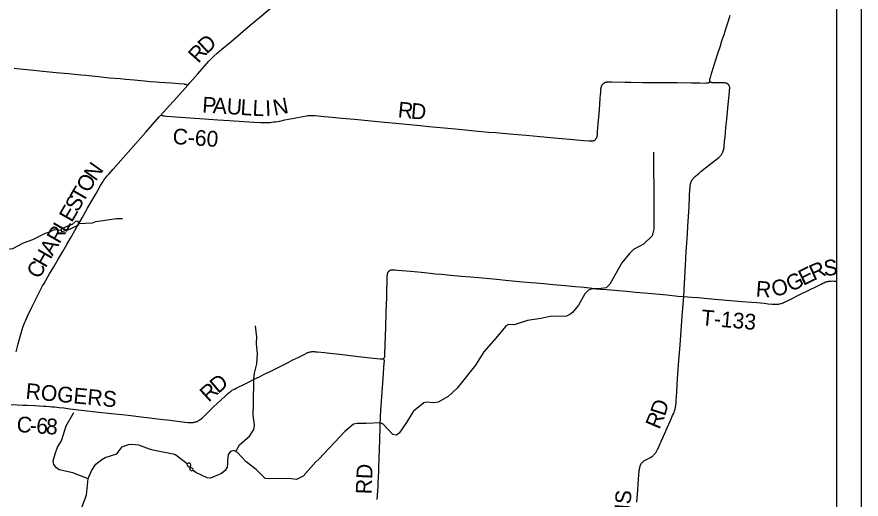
# Model space of a CAD drawing. Extents: x -5.4 to 49.9, y 13.2 to 48.4.
# Drawn here: x 30.118 to 33.165, y 44.845 to 46.585 of the extents above; entities that cross this region are included whole.
import ezdxf

# ---------------------------------------------------------------- set-up
doc = ezdxf.new("R2010")
doc.units = 0
for name, color, linetype in [('GM_X_County_Road', 7, 'Continuous'), ('GM_X_County_Road_Text', 7, 'Continuous'), ('GM_X_Major_River', 7, 'Continuous'), ('GM_X_Minor_Lake', 7, 'Continuous'), ('GM_X_Minor_River', 7, 'Continuous'), ('GM_X_Township', 7, 'Continuous'), ('GM_X_Township_Road', 7, 'Continuous'), ('GM_X_Township_Road_Text', 7, 'Continuous'), ('SH_Data', 7, 'Continuous')]:
    doc.layers.add(name, color=color, linetype=linetype)

msp = doc.modelspace()

# ---------------------------------------------------------------- linework, layer by layer
at = {"layer": 'GM_X_County_Road'}
for points in [[(30.7351, 46.3393), (30.7424, 46.3474), (30.7528, 46.3589), (30.7707, 46.3795), (30.8111, 46.4252), (30.8205, 46.4352), (30.8248, 46.4396), (30.8289, 46.4435), (30.8413, 46.4549), (30.8497, 46.4622), (30.8573, 46.4687), (30.8896, 46.4959), (30.9249, 46.5254), (30.9601, 46.5549), (30.9941, 46.5831), (31.0471, 46.6271)], [(30.6373, 46.2311), (30.6401, 46.2302), (30.6418, 46.2296), (30.6436, 46.2292), (30.646, 46.2286), (30.6485, 46.2281), (30.6515, 46.2277), (30.6577, 46.2271), (30.6918, 46.2248), (30.7427, 46.2213), (30.7786, 46.2187), (30.8431, 46.2143), (30.8846, 46.2117), (30.9727, 46.2059), (30.9981, 46.2044), (31.0093, 46.204), (31.0134, 46.204), (31.0174, 46.204), (31.0224, 46.2041), (31.0273, 46.2044), (31.0323, 46.2047), (31.0385, 46.2053), (31.0448, 46.206), (31.0514, 46.207), (31.059, 46.2082), (31.0667, 46.2095), (31.0856, 46.2133), (31.1246, 46.2211), (31.1502, 46.2262), (31.1629, 46.2285), (31.168, 46.2293), (31.1712, 46.2296), (31.1745, 46.2299), (31.1781, 46.23), (31.1814, 46.23), (31.1847, 46.2299), (31.1898, 46.2295), (31.1947, 46.2291), (31.2268, 46.2263), (31.2559, 46.2235), (31.2905, 46.2202), (31.3363, 46.2158), (31.3852, 46.2114), (31.4328, 46.2068), (31.486, 46.2018), (31.5738, 46.193), (31.6054, 46.19), (31.632, 46.1875), (31.6605, 46.1848), (31.6994, 46.1811), (31.7124, 46.1799), (31.7365, 46.1777), (31.7706, 46.1743), (31.8201, 46.1698), (31.8473, 46.1675), (31.8962, 46.1633), (31.9563, 46.158), (32.007, 46.1532), (32.0702, 46.148), (32.1271, 46.1431), (32.163, 46.1398), (32.1835, 46.1379), (32.1891, 46.1375), (32.1909, 46.1374), (32.1928, 46.1375), (32.1945, 46.1376), (32.1958, 46.1378), (32.1971, 46.138), (32.1984, 46.1383), (32.1997, 46.1387), (32.2012, 46.1393), (32.2023, 46.1398), (32.204, 46.1408), (32.2054, 46.1419), (32.2068, 46.1431), (32.2076, 46.144), (32.2082, 46.1448), (32.2091, 46.146), (32.21, 46.1476), (32.2109, 46.1495), (32.2115, 46.1511), (32.212, 46.1528), (32.2125, 46.1546), (32.2129, 46.1567), (32.2132, 46.1589), (32.214, 46.1676), (32.2154, 46.1856), (32.2175, 46.2123), (32.2193, 46.2352), (32.2219, 46.2674), (32.2239, 46.2934), (32.2246, 46.3027), (32.2253, 46.3133), (32.2256, 46.317), (32.2259, 46.3219), (32.2263, 46.3251), (32.2265, 46.3264), (32.2267, 46.3277), (32.227, 46.3294), (32.2274, 46.3313), (32.2278, 46.333), (32.2282, 46.3342), (32.2285, 46.3354), (32.2291, 46.3368), (32.2296, 46.3379), (32.2302, 46.3391), (32.231, 46.3404), (32.2318, 46.3415), (32.2327, 46.3427), (32.2337, 46.3437), (32.235, 46.345), (32.2362, 46.3459), (32.2375, 46.3468), (32.2386, 46.3474), (32.2402, 46.3483), (32.2418, 46.3489), (32.2429, 46.3493), (32.2445, 46.3497), (32.2459, 46.35), (32.2476, 46.3503), (32.2492, 46.3505), (32.2513, 46.3507), (32.2537, 46.3508), (32.2648, 46.3507), (32.312, 46.3496), (32.3338, 46.3494), (32.3773, 46.3491), (32.4077, 46.3489), (32.4512, 46.3485), (32.5016, 46.348), (32.5513, 46.3474), (32.5836, 46.3469), (32.601, 46.3467), (32.6072, 46.3468), (32.6091, 46.3469), (32.6109, 46.3471), (32.6122, 46.3473), (32.6134, 46.3475), (32.6145, 46.3479), (32.6158, 46.3484), (32.617, 46.3488), (32.6182, 46.3494), (32.6197, 46.35), (32.621, 46.3508)], [(30.6373, 46.2311), (30.6565, 46.2525), (30.6948, 46.2949), (30.7351, 46.3393)], [(30.1151, 45.3767), (30.1226, 45.4055), (30.1322, 45.4402), (30.1342, 45.4472), (30.1363, 45.454), (30.1379, 45.4593), (30.1399, 45.4652), (30.142, 45.4711), (30.1445, 45.4775), (30.147, 45.4837), (30.15, 45.4907), (30.1529, 45.4973), (30.1567, 45.5054), (30.1724, 45.5379), (30.189, 45.5719), (30.2004, 45.5948), (30.2108, 45.6146), (30.216, 45.6236), (30.2231, 45.6362), (30.2358, 45.6576), (30.251, 45.6832), (30.2661, 45.7089), (30.2836, 45.739), (30.2979, 45.7638), (30.3114, 45.7868), (30.332, 45.823), (30.3533, 45.8602), (30.3732, 45.8953), (30.3862, 45.9179), (30.4035, 45.9482), (30.4198, 45.9768), (30.4256, 45.9864), (30.4288, 45.9912), (30.432, 45.9956), (30.4355, 46.0004), (30.4395, 46.0056), (30.444, 46.0112), (30.4494, 46.0176), (30.4653, 46.0359), (30.5191, 46.097), (30.5831, 46.1698), (30.6316, 46.2247), (30.6373, 46.2311)], [(31.4417, 45.3527), (31.4422, 45.3531), (31.4429, 45.3537), (31.4436, 45.3544), (31.4442, 45.3552), (31.4446, 45.3558), (31.445, 45.3565), (31.4453, 45.3573), (31.4456, 45.3581), (31.4458, 45.359), (31.4461, 45.3622), (31.4465, 45.3709), (31.4475, 45.4001), (31.4486, 45.4324), (31.4497, 45.4659), (31.4513, 45.52), (31.4527, 45.574), (31.4537, 45.6044), (31.4543, 45.6243), (31.4546, 45.6374), (31.4548, 45.6479), (31.455, 45.6511), (31.4552, 45.6537), (31.4555, 45.6558), (31.4559, 45.6577), (31.4562, 45.6593), (31.4566, 45.6605), (31.457, 45.6616), (31.4574, 45.6626), (31.4579, 45.6637), (31.4585, 45.6648), (31.4592, 45.6657), (31.46, 45.6666), (31.4609, 45.6677), (31.4619, 45.6685), (31.4628, 45.6692), (31.4638, 45.6699), (31.4648, 45.6706), (31.4658, 45.6711), (31.467, 45.6716), (31.4681, 45.672), (31.4695, 45.6724), (31.4711, 45.6726), (31.4723, 45.6727), (31.4738, 45.6728), (31.4754, 45.6729), (31.4775, 45.6729), (31.4795, 45.6728), (31.4836, 45.6724), (31.4935, 45.6715), (31.5079, 45.67), (31.5387, 45.6673), (31.5647, 45.6648), (31.5889, 45.6623), (31.6093, 45.6604), (31.6291, 45.6585), (31.6501, 45.6564), (31.6835, 45.6533), (31.7229, 45.6498), (31.7558, 45.6469), (31.7851, 45.6442), (31.8377, 45.6394), (31.8607, 45.6371), (31.8815, 45.6351), (31.9068, 45.6329), (31.9445, 45.6294), (31.9724, 45.6268), (31.9928, 45.625), (32.0194, 45.6226), (32.0543, 45.6195), (32.0966, 45.6157), (32.1332, 45.6124), (32.1656, 45.6093), (32.1942, 45.6059), (32.2015, 45.605), (32.2084, 45.6044), (32.2243, 45.603), (32.2476, 45.6011), (32.3182, 45.5953), (32.351, 45.5923), (32.3826, 45.5894), (32.424, 45.5855), (32.4634, 45.5817), (32.5035, 45.5777), (32.5249, 45.576)], [(30.0967, 45.1867), (30.1188, 45.1854), (30.1402, 45.1843), (30.1544, 45.1836), (30.1832, 45.1823), (30.2136, 45.1808), (30.2235, 45.1803), (30.2353, 45.1794), (30.2445, 45.1785), (30.2537, 45.1776), (30.2704, 45.1758), (30.2868, 45.1739), (30.3092, 45.1712), (30.3402, 45.1672), (30.3718, 45.1634), (30.3926, 45.1611), (30.4251, 45.1578), (30.4474, 45.1556), (30.4716, 45.1531), (30.497, 45.1505), (30.5196, 45.1479), (30.5387, 45.1455), (30.5567, 45.1432), (30.5759, 45.1407), (30.5979, 45.138), (30.6246, 45.1348), (30.6472, 45.1321), (30.6711, 45.1292), (30.6982, 45.126), (30.7244, 45.123), (30.735, 45.1217), (30.7411, 45.1211), (30.7458, 45.1208), (30.7488, 45.1209), (30.7513, 45.1212), (30.7539, 45.1216), (30.7564, 45.1221), (30.7604, 45.123), (30.7627, 45.1235), (30.7649, 45.1242), (30.7666, 45.1248), (30.7681, 45.1254), (30.7702, 45.1263), (30.772, 45.1273), (30.7738, 45.1282), (30.7758, 45.1293), (30.7777, 45.1306), (30.7799, 45.1321), (30.7834, 45.1347), (30.7882, 45.1386), (30.7914, 45.1416), (30.805, 45.155), (30.8161, 45.1661), (30.828, 45.1776), (30.8411, 45.1899), (30.8545, 45.2023), (30.8697, 45.2164), (30.8786, 45.2245), (30.8838, 45.2291), (30.8874, 45.232), (30.89, 45.234), (30.8912, 45.235), (30.8927, 45.2361), (30.8954, 45.2378), (30.898, 45.2393), (30.9036, 45.2422), (30.9099, 45.2454), (30.9166, 45.2486), (30.9348, 45.2575), (30.9543, 45.2672), (30.9743, 45.2772), (30.9932, 45.2867), (31.011, 45.2955), (31.0272, 45.3033), (31.0485, 45.314), (31.0824, 45.331), (31.0968, 45.3382), (31.1144, 45.347), (31.1355, 45.3576), (31.1472, 45.3635), (31.1622, 45.371), (31.165, 45.3723), (31.1679, 45.3735), (31.1706, 45.3745), (31.1734, 45.3754), (31.1759, 45.3761), (31.1771, 45.3763), (31.1781, 45.3765), (31.1804, 45.3768), (31.183, 45.3771), (31.1852, 45.3773), (31.1873, 45.3773), (31.1891, 45.3773), (31.1924, 45.3771), (31.1953, 45.377), (31.1976, 45.3768), (31.2028, 45.3764), (31.2288, 45.3736), (31.2481, 45.3715), (31.2832, 45.3675), (31.33, 45.362), (31.3615, 45.3585), (31.3937, 45.3549), (31.4177, 45.3521), (31.4294, 45.3511), (31.4321, 45.3508), (31.4343, 45.3507), (31.4363, 45.3507), (31.4373, 45.3508), (31.4383, 45.351), (31.4392, 45.3513), (31.44, 45.3516), (31.4408, 45.3521), (31.4417, 45.3527)]]:
    msp.add_lwpolyline(points, dxfattribs=at)
at = {"layer": 'GM_X_Major_River'}
for points in [[(32.4155, 46.097), (32.417, 45.9063), (32.4167, 45.8186), (32.4106, 45.7951), (32.3801, 45.765), (32.3441, 45.746), (32.3295, 45.7318), (32.3016, 45.6982), (32.2588, 45.6205), (32.2449, 45.6078), (32.2191, 45.6038), (32.1949, 45.6039), (32.1812, 45.5989), (32.168, 45.5855), (32.1453, 45.5453), (32.124, 45.5188), (32.1143, 45.5106), (32.1014, 45.5056), (32.0431, 45.5041), (32.0199, 45.4992), (32.0096, 45.4964), (31.9614, 45.4898), (31.9127, 45.4741), (31.8923, 45.4749), (31.8812, 45.4683), (31.8463, 45.4253), (31.8033, 45.3764), (31.7732, 45.3284), (31.7072, 45.2451), (31.6745, 45.215), (31.6389, 45.1944), (31.6218, 45.1925), (31.5969, 45.1949), (31.5866, 45.1921), (31.5497, 45.1617), (31.5317, 45.1332), (31.5239, 45.1216), (31.4974, 45.0826), (31.4878, 45.0752), (31.4754, 45.0785), (31.4402, 45.1149), (31.4304, 45.1204), (31.3786, 45.118), (31.3457, 45.1183), (31.3324, 45.1156), (31.3016, 45.0885), (31.2076, 44.9893), (31.1965, 44.9789), (31.1508, 44.9282), (31.1267, 44.9158), (31.0999, 44.9194), (31.0258, 44.9186), (31.014, 44.9196), (30.9814, 44.9518), (30.9452, 44.9791), (30.9145, 45.0127), (30.9007, 45.0199), (30.8893, 45.0171), (30.8807, 45.0062), (30.8784, 44.9846), (30.8781, 44.9717), (30.8768, 44.9607), (30.8697, 44.9483), (30.8563, 44.9372), (30.8162, 44.9202), (30.8045, 44.9212), (30.7636, 44.9406), (30.7522, 44.9489)], [(30.2375, 44.6265), (30.2685, 44.6593), (30.3288, 44.7428), (30.341, 44.7703), (30.3457, 44.793), (30.3528, 44.8073), (30.3537, 44.8179), (30.3689, 44.859), (30.3758, 44.9196), (30.3869, 44.9463), (30.4033, 44.9707), (30.4248, 44.9881), (30.4363, 44.9955), (30.479, 45.0086), (30.498, 45.0333), (30.5209, 45.0416), (30.533, 45.0433), (30.5572, 45.0409), (30.5955, 45.0264), (30.6083, 45.0227), (30.6821, 45.0083), (30.6919, 45.0043), (30.7325, 44.9739)], [(30.7325, 44.9739), (30.7318, 44.971), (30.7324, 44.9671), (30.7346, 44.964), (30.7372, 44.9616), (30.7406, 44.9616), (30.7444, 44.963), (30.746, 44.9656), (30.7457, 44.9691), (30.7442, 44.9729), (30.7413, 44.9742), (30.739, 44.9749), (30.7363, 44.975), (30.7356, 44.9746)], [(30.7325, 44.9739), (30.7356, 44.9746)], [(30.7412, 44.9536), (30.7423, 44.952), (30.7445, 44.9493), (30.7471, 44.9478), (30.7494, 44.9473), (30.7513, 44.9481), (30.7525, 44.9492), (30.7537, 44.9526), (30.753, 44.9553), (30.75, 44.9568), (30.747, 44.958), (30.7454, 44.9577)], [(30.7454, 44.9577), (30.7412, 44.9536)]]:
    msp.add_lwpolyline(points, dxfattribs=at)
at = {"layer": 'GM_X_Minor_Lake'}
for points in [[(30.2786, 45.8106), (30.2991, 45.8159), (30.3136, 45.8214), (30.3351, 45.8324), (30.3412, 45.8364), (30.3395, 45.8486), (30.3289, 45.8473), (30.3173, 45.8365), (30.3036, 45.8318), (30.2872, 45.8238), (30.2787, 45.8197)], [(30.2787, 45.8197), (30.2775, 45.8185), (30.2768, 45.8163), (30.2772, 45.8126), (30.2786, 45.8106)], [(30.2375, 44.6265), (30.2685, 44.6593), (30.3288, 44.7428), (30.341, 44.7703), (30.3457, 44.793), (30.3528, 44.8073), (30.3537, 44.8179), (30.3689, 44.859), (30.3758, 44.9196), (30.3869, 44.9463), (30.4033, 44.9707), (30.4248, 44.9881), (30.4363, 44.9955), (30.479, 45.0086), (30.498, 45.0333), (30.5209, 45.0416), (30.533, 45.0433), (30.5572, 45.0409), (30.5955, 45.0264), (30.6083, 45.0227), (30.6821, 45.0083), (30.6919, 45.0043), (30.7325, 44.9739)]]:
    msp.add_lwpolyline(points, dxfattribs=at)
at = {"layer": 'GM_X_Minor_River'}
for points in [[(30.3408, 45.8393), (30.3913, 45.842), (30.4031, 45.8463), (30.478, 45.8579), (30.4996, 45.8579)], [(29.3473, 45.56), (29.3917, 45.5706), (29.4934, 45.6212), (29.5186, 45.6299), (29.6255, 45.6534), (29.6936, 45.6909), (29.7377, 45.7167), (29.7686, 45.7302), (29.8055, 45.7368), (29.862, 45.738), (30.0475, 45.7533), (30.0804, 45.747), (30.1035, 45.7492), (30.1418, 45.7698), (30.1754, 45.7813), (30.2213, 45.8044), (30.2331, 45.8084), (30.2541, 45.8183), (30.2769, 45.8155)], [(30.908, 45.0161), (30.922, 45.0406), (30.9578, 45.0723), (30.9734, 45.0963), (30.9752, 45.1115), (30.9713, 45.1477), (30.972, 45.1895), (30.9728, 45.2776), (30.9751, 45.2989), (30.984, 45.3336), (30.987, 45.3693), (30.9831, 45.4066), (30.9846, 45.429), (30.9793, 45.4706)], [(30.3757, 44.9185), (30.3199, 44.9391), (30.2705, 44.9507), (30.2607, 44.9573), (30.2518, 44.9696), (30.2487, 44.9826), (30.2556, 45.0083), (30.264, 45.0329), (30.2784, 45.0546), (30.296, 45.1098), (30.3238, 45.1572)]]:
    msp.add_lwpolyline(points, dxfattribs=at)
at = {"layer": 'GM_X_Township'}
msp.add_lwpolyline([(33.0771, 44.431), (33.0771, 47.4437), (28.0105, 47.4437)], dxfattribs=at)
at = {"layer": 'GM_X_Township_Road'}
for points in [[(32.621, 46.3508), (32.6205, 46.3515), (32.6201, 46.3524), (32.6198, 46.3532), (32.6196, 46.3541), (32.6194, 46.355), (32.6194, 46.3563), (32.6194, 46.3575), (32.6194, 46.3584), (32.6196, 46.3596), (32.6198, 46.3606), (32.6211, 46.366), (32.624, 46.3761), (32.6316, 46.4004), (32.6376, 46.4194), (32.6485, 46.4531), (32.6573, 46.4804), (32.6631, 46.4988), (32.6704, 46.5213), (32.6784, 46.5462), (32.6867, 46.5717), (32.6931, 46.5917)], [(30.1084, 46.4003), (30.1288, 46.3983), (30.1671, 46.3943), (30.211, 46.39), (30.2593, 46.3852), (30.3044, 46.3808), (30.3489, 46.3763), (30.3662, 46.3745), (30.378, 46.3733), (30.3891, 46.3722), (30.4218, 46.3688), (30.4521, 46.3658), (30.4905, 46.3624), (30.5112, 46.3604), (30.5412, 46.3577), (30.5787, 46.3544), (30.6004, 46.3527), (30.6219, 46.3509), (30.633, 46.3501), (30.6544, 46.3486), (30.6761, 46.3472), (30.7023, 46.345), (30.7212, 46.3432), (30.7235, 46.343), (30.7254, 46.3427), (30.7275, 46.3423), (30.729, 46.3418), (30.732, 46.3406), (30.7351, 46.3393)], [(32.5249, 45.576), (32.5264, 45.5995), (32.5278, 45.6272), (32.5284, 45.6396), (32.5302, 45.67), (32.5313, 45.6874), (32.5329, 45.7134), (32.5342, 45.7376), (32.5362, 45.7686), (32.5383, 45.8021), (32.5399, 45.8306), (32.5441, 45.9001), (32.5461, 45.9367), (32.5474, 45.9646), (32.5477, 45.9689), (32.5481, 45.9729), (32.5485, 45.9757), (32.5488, 45.9782), (32.549, 45.9798), (32.5493, 45.981), (32.5496, 45.9824), (32.5499, 45.9839), (32.5504, 45.9855), (32.5511, 45.9875), (32.5516, 45.989), (32.5521, 45.9904), (32.5529, 45.9921), (32.5535, 45.9933), (32.5541, 45.9945), (32.5548, 45.9956), (32.5556, 45.9969), (32.5565, 45.9983), (32.5579, 46.0002), (32.5591, 46.0018), (32.5627, 46.0061), (32.5676, 46.0109), (32.5732, 46.0158), (32.5804, 46.0217), (32.5872, 46.0272), (32.615, 46.0491), (32.6408, 46.0696), (32.6516, 46.0784), (32.6549, 46.0815), (32.6566, 46.0831), (32.6579, 46.0844), (32.6589, 46.0856), (32.66, 46.087), (32.6612, 46.0885), (32.6622, 46.09), (32.6629, 46.0912), (32.664, 46.0929), (32.6649, 46.0946), (32.6657, 46.0962), (32.6662, 46.0974), (32.6666, 46.0985), (32.6672, 46.1), (32.6678, 46.1014), (32.6684, 46.1034), (32.6688, 46.105), (32.6692, 46.1068), (32.6695, 46.1086), (32.6698, 46.1105), (32.6704, 46.1143), (32.671, 46.1191), (32.6726, 46.1358), (32.674, 46.1507), (32.6771, 46.1853), (32.6802, 46.2168), (32.6852, 46.2694), (32.6888, 46.3028), (32.6901, 46.3164), (32.6907, 46.3227), (32.6911, 46.3271), (32.6911, 46.3284), (32.6911, 46.3297), (32.691, 46.3308), (32.6909, 46.3319), (32.6905, 46.3337), (32.6902, 46.3348), (32.6898, 46.3358), (32.6895, 46.3368), (32.689, 46.3377), (32.6882, 46.339), (32.6876, 46.3399), (32.687, 46.3406), (32.6864, 46.3414), (32.6856, 46.3421), (32.6843, 46.3431), (32.6831, 46.3439), (32.682, 46.3445), (32.681, 46.3451), (32.6795, 46.3457), (32.6786, 46.3461), (32.6776, 46.3464), (32.6766, 46.3466), (32.6757, 46.3467), (32.6739, 46.3468), (32.6707, 46.3469), (32.6651, 46.347), (32.652, 46.347), (32.6408, 46.347), (32.6337, 46.3471), (32.6298, 46.3472), (32.6282, 46.3474), (32.6268, 46.3476), (32.6257, 46.3478), (32.6249, 46.348), (32.6239, 46.3485), (32.6231, 46.3489), (32.6223, 46.3495), (32.6217, 46.35), (32.621, 46.3508)], [(32.5249, 45.576), (32.5539, 45.5739), (32.5773, 45.572), (32.6116, 45.5691), (32.6518, 45.5656), (32.6936, 45.5621), (32.7363, 45.5584), (32.7708, 45.5555), (32.7886, 45.5539), (32.8152, 45.5515), (32.83, 45.5502), (32.8457, 45.5488), (32.8526, 45.5483), (32.8563, 45.5482), (32.8594, 45.548), (32.8623, 45.548), (32.8636, 45.548), (32.8647, 45.5481), (32.8658, 45.5482), (32.8667, 45.5484), (32.8682, 45.5486), (32.8703, 45.5491), (32.875, 45.5504), (32.8781, 45.5513), (32.8815, 45.5525), (32.8847, 45.5539), (32.8883, 45.5555), (32.9017, 45.5621), (32.914, 45.568), (32.9419, 45.5818), (32.9812, 45.6016), (33.0013, 45.6116), (33.0208, 45.6212), (33.027, 45.6242), (33.0311, 45.626), (33.0344, 45.6274), (33.036, 45.628), (33.0378, 45.6286), (33.04, 45.6293), (33.0424, 45.6299), (33.044, 45.6304), (33.046, 45.6308), (33.0479, 45.6312), (33.0496, 45.6314), (33.0512, 45.6316), (33.0536, 45.6318), (33.0566, 45.6319), (33.0615, 45.6321), (33.0668, 45.632), (33.0723, 45.6318), (33.0771, 45.6315)], [(32.3561, 44.8337), (32.3593, 44.8789), (32.3607, 44.8981), (32.362, 44.9161), (32.3632, 44.9334), (32.3641, 44.9438), (32.3646, 44.9486), (32.3651, 44.9519), (32.3656, 44.9547), (32.3661, 44.9574), (32.3666, 44.9595), (32.367, 44.9611), (32.3675, 44.963), (32.3682, 44.9649), (32.3688, 44.9664), (32.3694, 44.9682), (32.3701, 44.9696), (32.3709, 44.9712), (32.3719, 44.9729), (32.3728, 44.9742), (32.3738, 44.9753), (32.3752, 44.9768), (32.3767, 44.9783), (32.3783, 44.9798), (32.3802, 44.9814), (32.3823, 44.983), (32.3839, 44.9841), (32.3862, 44.9855), (32.391, 44.9882), (32.3983, 44.9917), (32.4055, 44.9955), (32.4111, 44.9993), (32.4141, 45.0015), (32.416, 45.0032), (32.4176, 45.0048), (32.4193, 45.0066), (32.4207, 45.0082), (32.4219, 45.0098), (32.4231, 45.0114), (32.4242, 45.0129), (32.4254, 45.0148), (32.4265, 45.0164), (32.4273, 45.0179), (32.4284, 45.0197), (32.4294, 45.0217), (32.4306, 45.0239), (32.4322, 45.0274), (32.434, 45.0312), (32.4376, 45.0398), (32.4399, 45.0448), (32.4436, 45.0534), (32.4467, 45.0602), (32.4492, 45.0658), (32.452, 45.0721), (32.458, 45.0857), (32.4654, 45.1022), (32.4774, 45.1288), (32.485, 45.1465), (32.4877, 45.1528), (32.49, 45.1585), (32.4917, 45.1632), (32.4922, 45.1648), (32.4926, 45.1661), (32.4931, 45.1675), (32.4935, 45.1689), (32.4938, 45.1701), (32.4941, 45.1715), (32.4947, 45.1737), (32.4951, 45.1757), (32.4955, 45.1779), (32.4958, 45.1795), (32.496, 45.1811), (32.4961, 45.1825), (32.4965, 45.1857), (32.4971, 45.1912), (32.4977, 45.1986), (32.4988, 45.2173), (32.4997, 45.2302), (32.5017, 45.2596), (32.5043, 45.2971), (32.5079, 45.3455), (32.512, 45.4006), (32.5174, 45.47), (32.5198, 45.5035), (32.5229, 45.5481), (32.5249, 45.576)], [(31.4179, 44.8431), (31.4204, 44.8749), (31.4215, 44.8921), (31.4223, 44.9059), (31.423, 44.9208), (31.424, 44.9488), (31.4246, 44.9661), (31.4252, 44.9854), (31.4266, 45.0313), (31.4275, 45.053), (31.4281, 45.0692), (31.4287, 45.0959), (31.4291, 45.1083), (31.4296, 45.1214), (31.4301, 45.1332), (31.4308, 45.1441), (31.4334, 45.1821), (31.4356, 45.2156), (31.4403, 45.2807), (31.4429, 45.3185), (31.4442, 45.337), (31.4445, 45.343), (31.4445, 45.3443), (31.4445, 45.3453), (31.4444, 45.3461), (31.4442, 45.3469), (31.444, 45.3476), (31.4429, 45.35), (31.4417, 45.3527)]]:
    msp.add_lwpolyline(points, dxfattribs=at)
at = {"layer": 'SH_Data'}
msp.add_line((33.1653, 47.5483), (33.1653, 40.5483), dxfattribs=at)

# ---------------------------------------------------------------- texts
at = {"layer": 'GM_X_County_Road_Text'}
for s, height, rotation, p in [('D', 0.0568, 42.9801, (30.8032, 46.449)), ('R', 0.0568, 48.0041, (30.7729, 46.4153)), ('P', 0.0568, 356.215, (30.7857, 46.2408)), ('A', 0.0568, 356.2123, (30.824, 46.2382)), ('U', 0.0568, 356.2149, (30.8739, 46.2349)), ('N', 0.0568, 11.0056, (31.0479, 46.2289)), ('L', 0.0568, 356.2486, (30.9238, 46.2316)), ('L', 0.0568, 357.1496, (30.9672, 46.2288)), ('I', 0.0568, 2.7323, (31.0157, 46.2267)), ('R', 0.0568, 354.4059, (31.4914, 46.2232)), ('D', 0.0568, 354.891, (31.5384, 46.2186)), ('C-60', 0.05682, 356.23, (30.6788, 46.1266)), ('N', 0.0568, 54.583, (30.4019, 45.9897)), ('O', 0.0568, 59.9971, (30.3776, 45.9476)), ('T', 0.0568, 60.0444, (30.3564, 45.9108)), ('S', 0.0568, 60.0394, (30.3373, 45.8776)), ('E', 0.0568, 60.0444, (30.316, 45.8408)), ('L', 0.0568, 60.0444, (30.2948, 45.8039)), ('R', 0.0568, 60.0397, (30.2715, 45.7635)), ('A', 0.0568, 60.0416, (30.2465, 45.7202)), ('H', 0.0568, 60.0416, (30.2216, 45.6769)), ('C', 0.0568, 60.0416, (30.1983, 45.6364)), ('D', 0.0568, 40.188, (30.844, 45.2235)), ('ROGERS', 0.05682, 354.5149, (30.1477, 45.2075)), ('R', 0.0568, 42.3635, (30.81, 45.1924)), ('C', 0.0568, 354.9625, (30.1152, 45.088)), ('6', 0.0568, 356.3314, (30.1865, 45.0823)), ('8', 0.0568, 356.4951, (30.2216, 45.08)), ('-', 0.0568, 356.307, (30.1631, 45.0838))]:
    msp.add_text(s, height=height, rotation=rotation, dxfattribs=at).set_placement(p)
at = {"layer": 'GM_X_Township_Road_Text'}
for s, height, rotation, p in [('S', 0.0568, 4.4279, (33.0318, 45.6504)), ('E', 0.0568, 26.1722, (32.9564, 45.6142)), ('R', 0.0568, 23.8725, (32.994, 45.6327)), ('G', 0.0568, 27.5723, (32.9124, 45.5912)), ('R', 0.0568, 355.683, (32.7838, 45.5765)), ('O', 0.0568, 13.114, (32.8491, 45.5745)), ('T-133', 0.05682, 354.9573, (32.586, 45.4727)), ('D', 0.0568, 71.9316, (32.4568, 45.1415)), ('R', 0.0568, 67.2462, (32.437, 45.0938)), ('RD', 0.05682, 87.6543, (31.3978, 44.8615)), ('WATKINS', 0.05682, 85.7018, (32.3111, 44.5302))]:
    msp.add_text(s, height=height, rotation=rotation, dxfattribs=at).set_placement(p)

doc.saveas('drawing.dxf')
